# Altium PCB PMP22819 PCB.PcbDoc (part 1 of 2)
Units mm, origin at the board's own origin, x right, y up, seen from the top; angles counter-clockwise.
Board outline 101.6 x 76.2 mm, 4 copper layers (Top Layer, Mid-Layer 1, Mid-Layer 2, Bottom Layer), stack 2.286 mm thick; 108 components, 51 nets, 288 pads, 278 vias.
Unrouted connection lines stored in the file: 1.
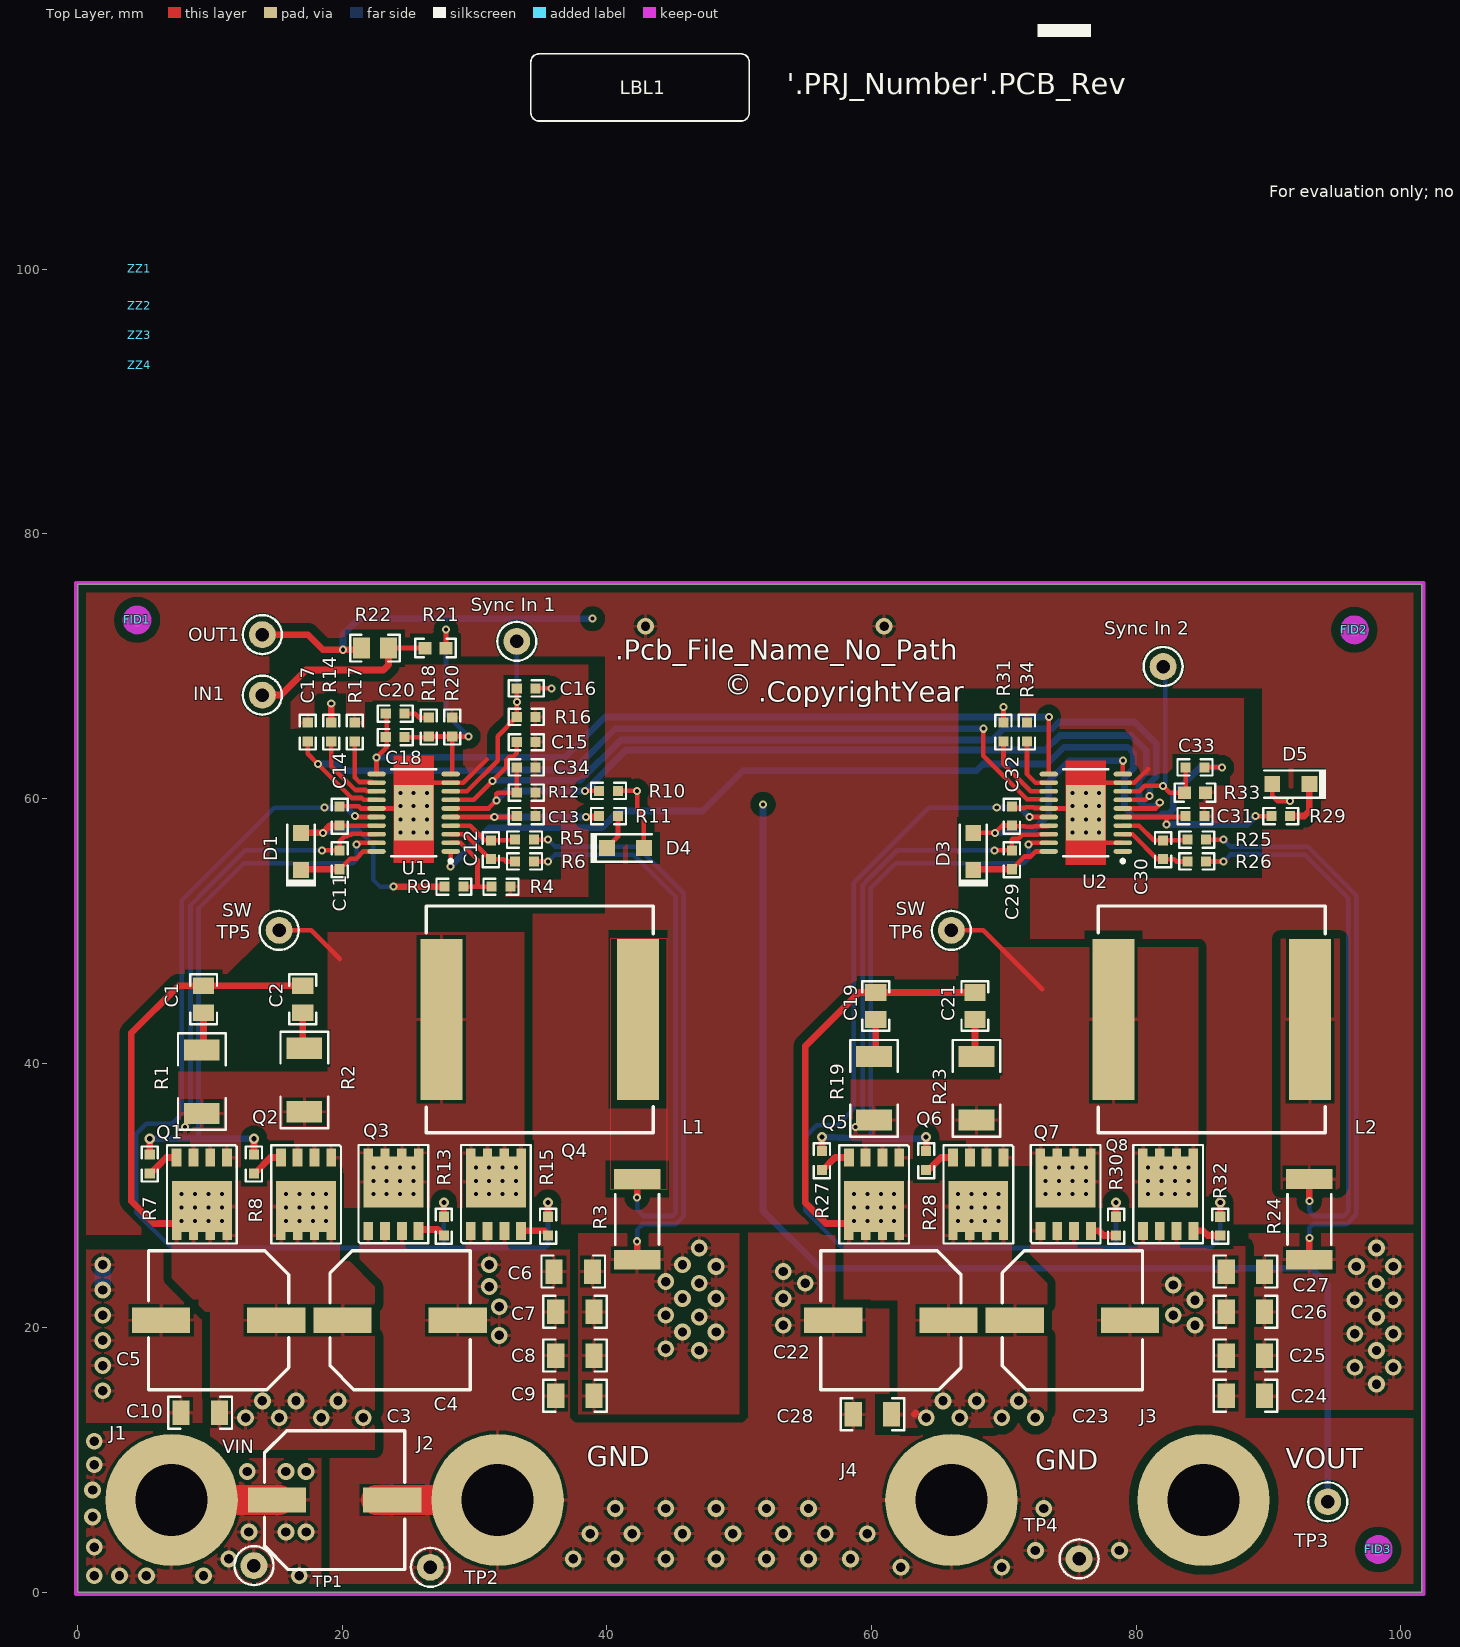
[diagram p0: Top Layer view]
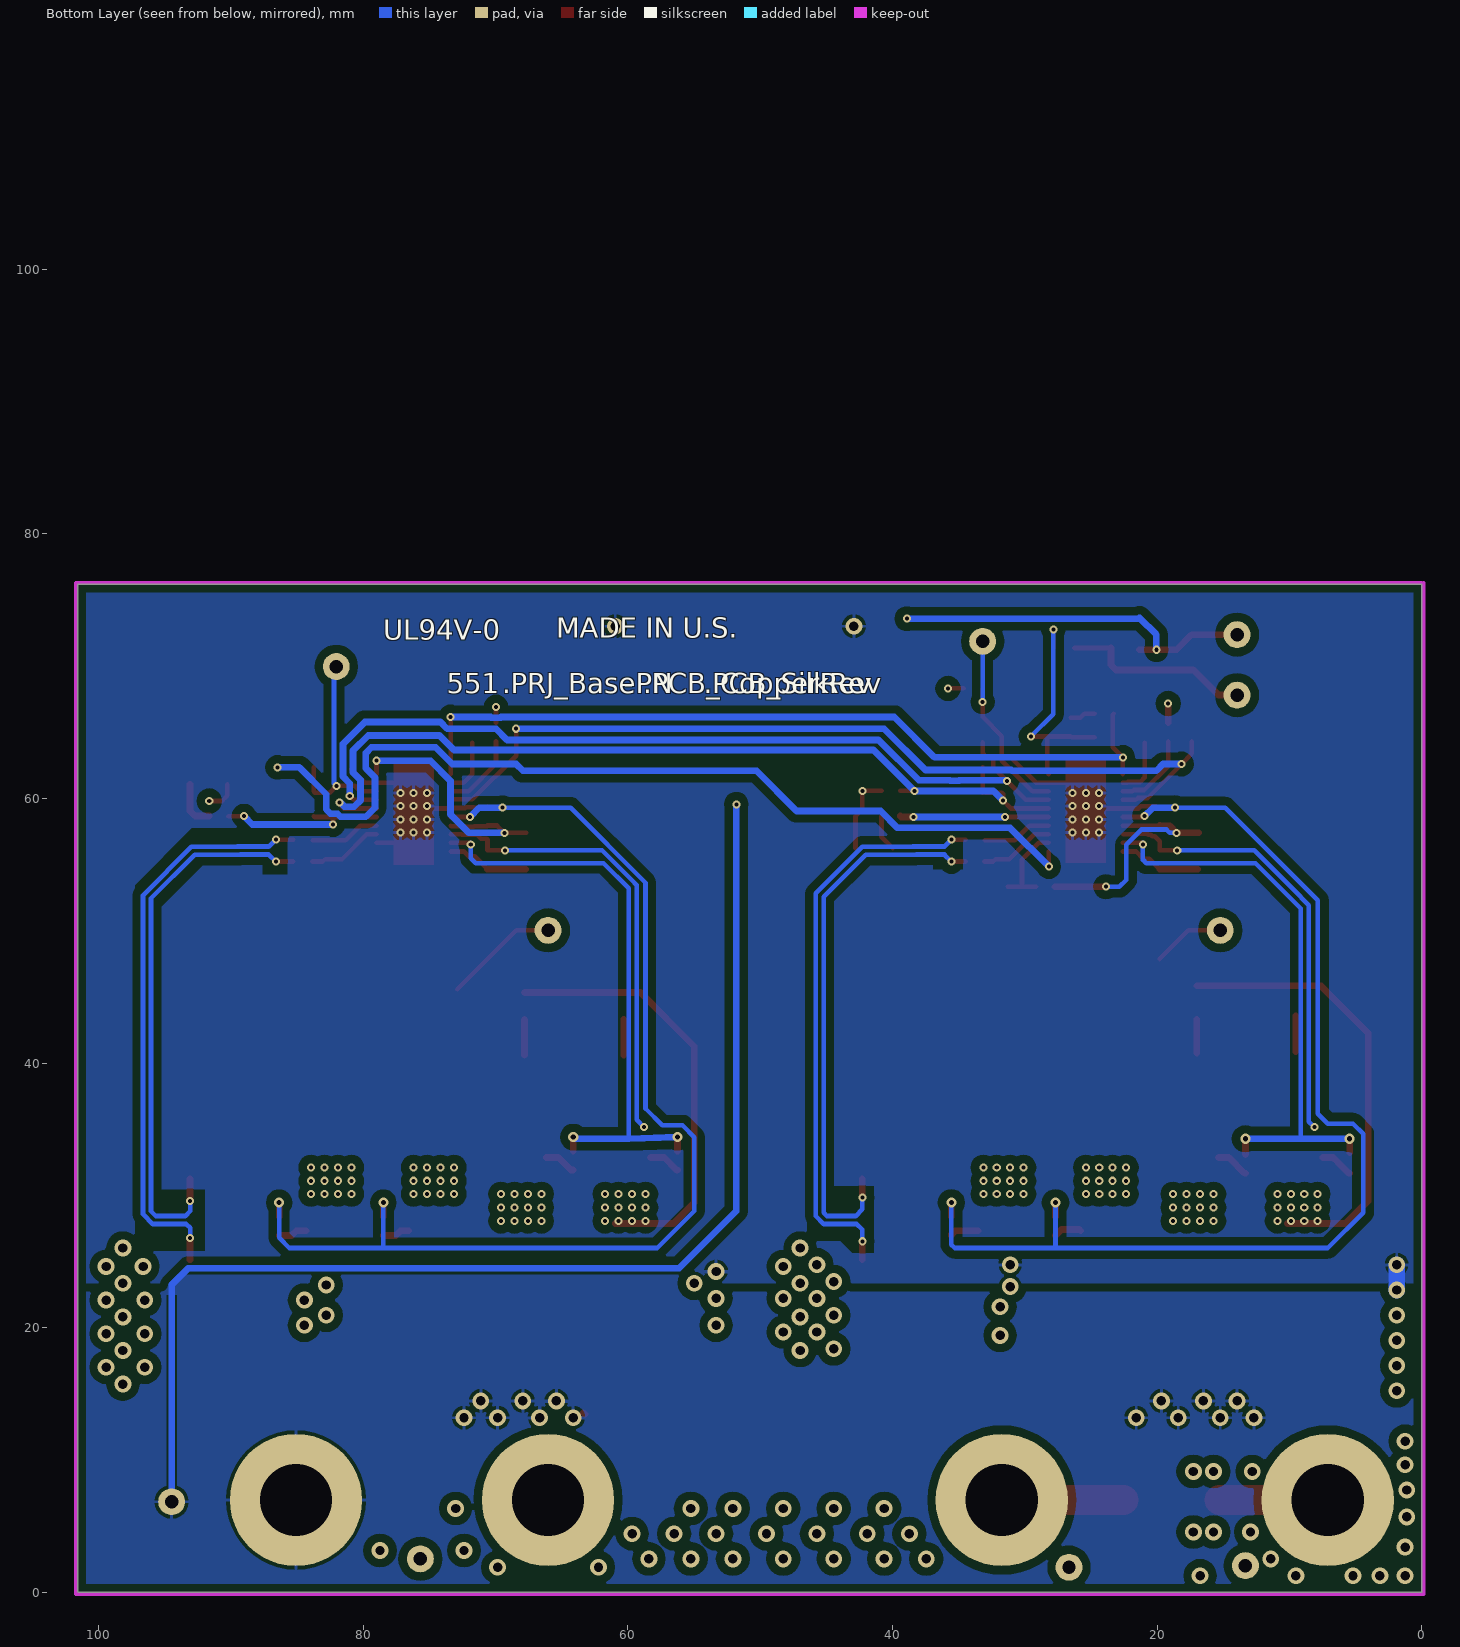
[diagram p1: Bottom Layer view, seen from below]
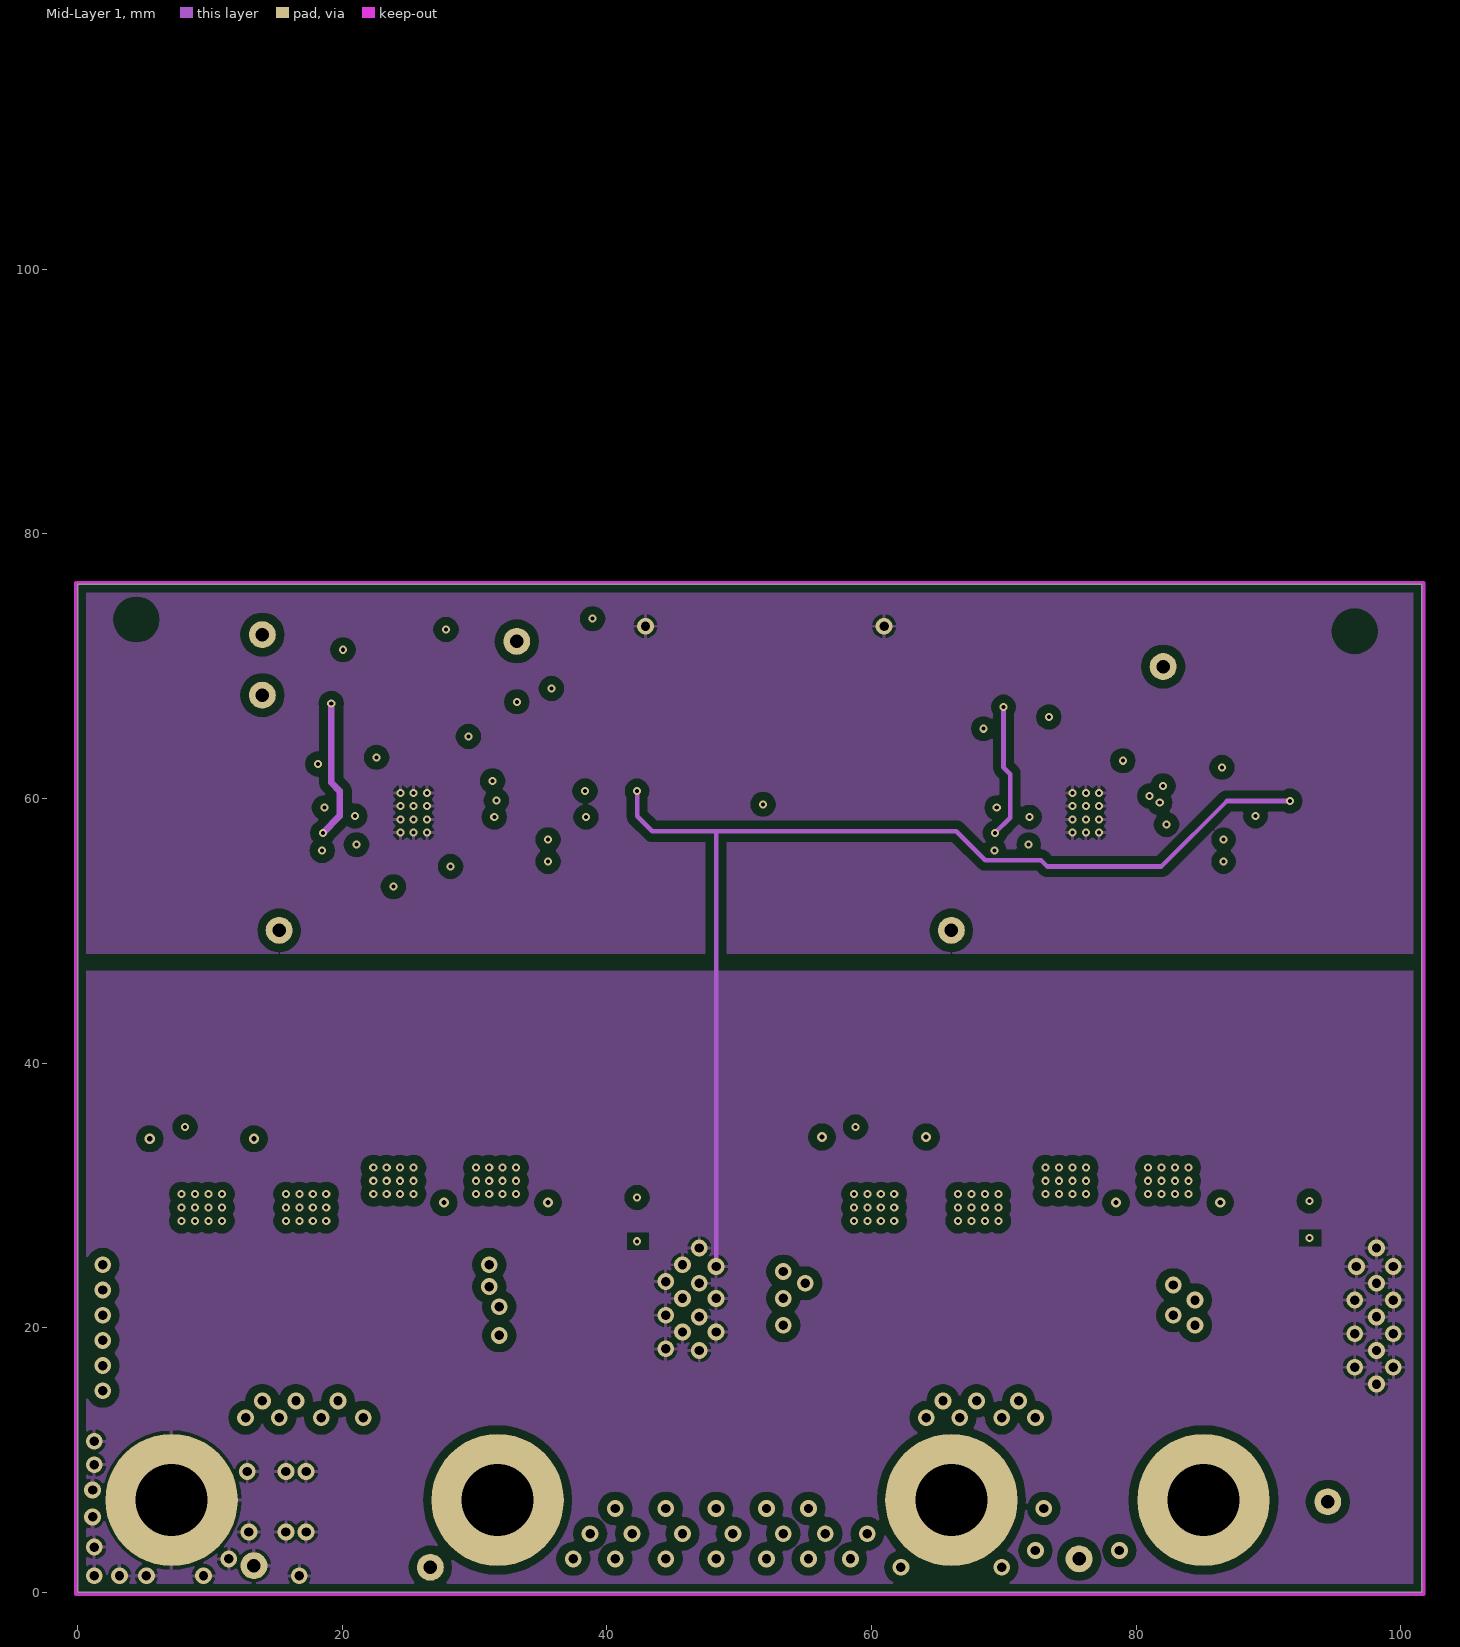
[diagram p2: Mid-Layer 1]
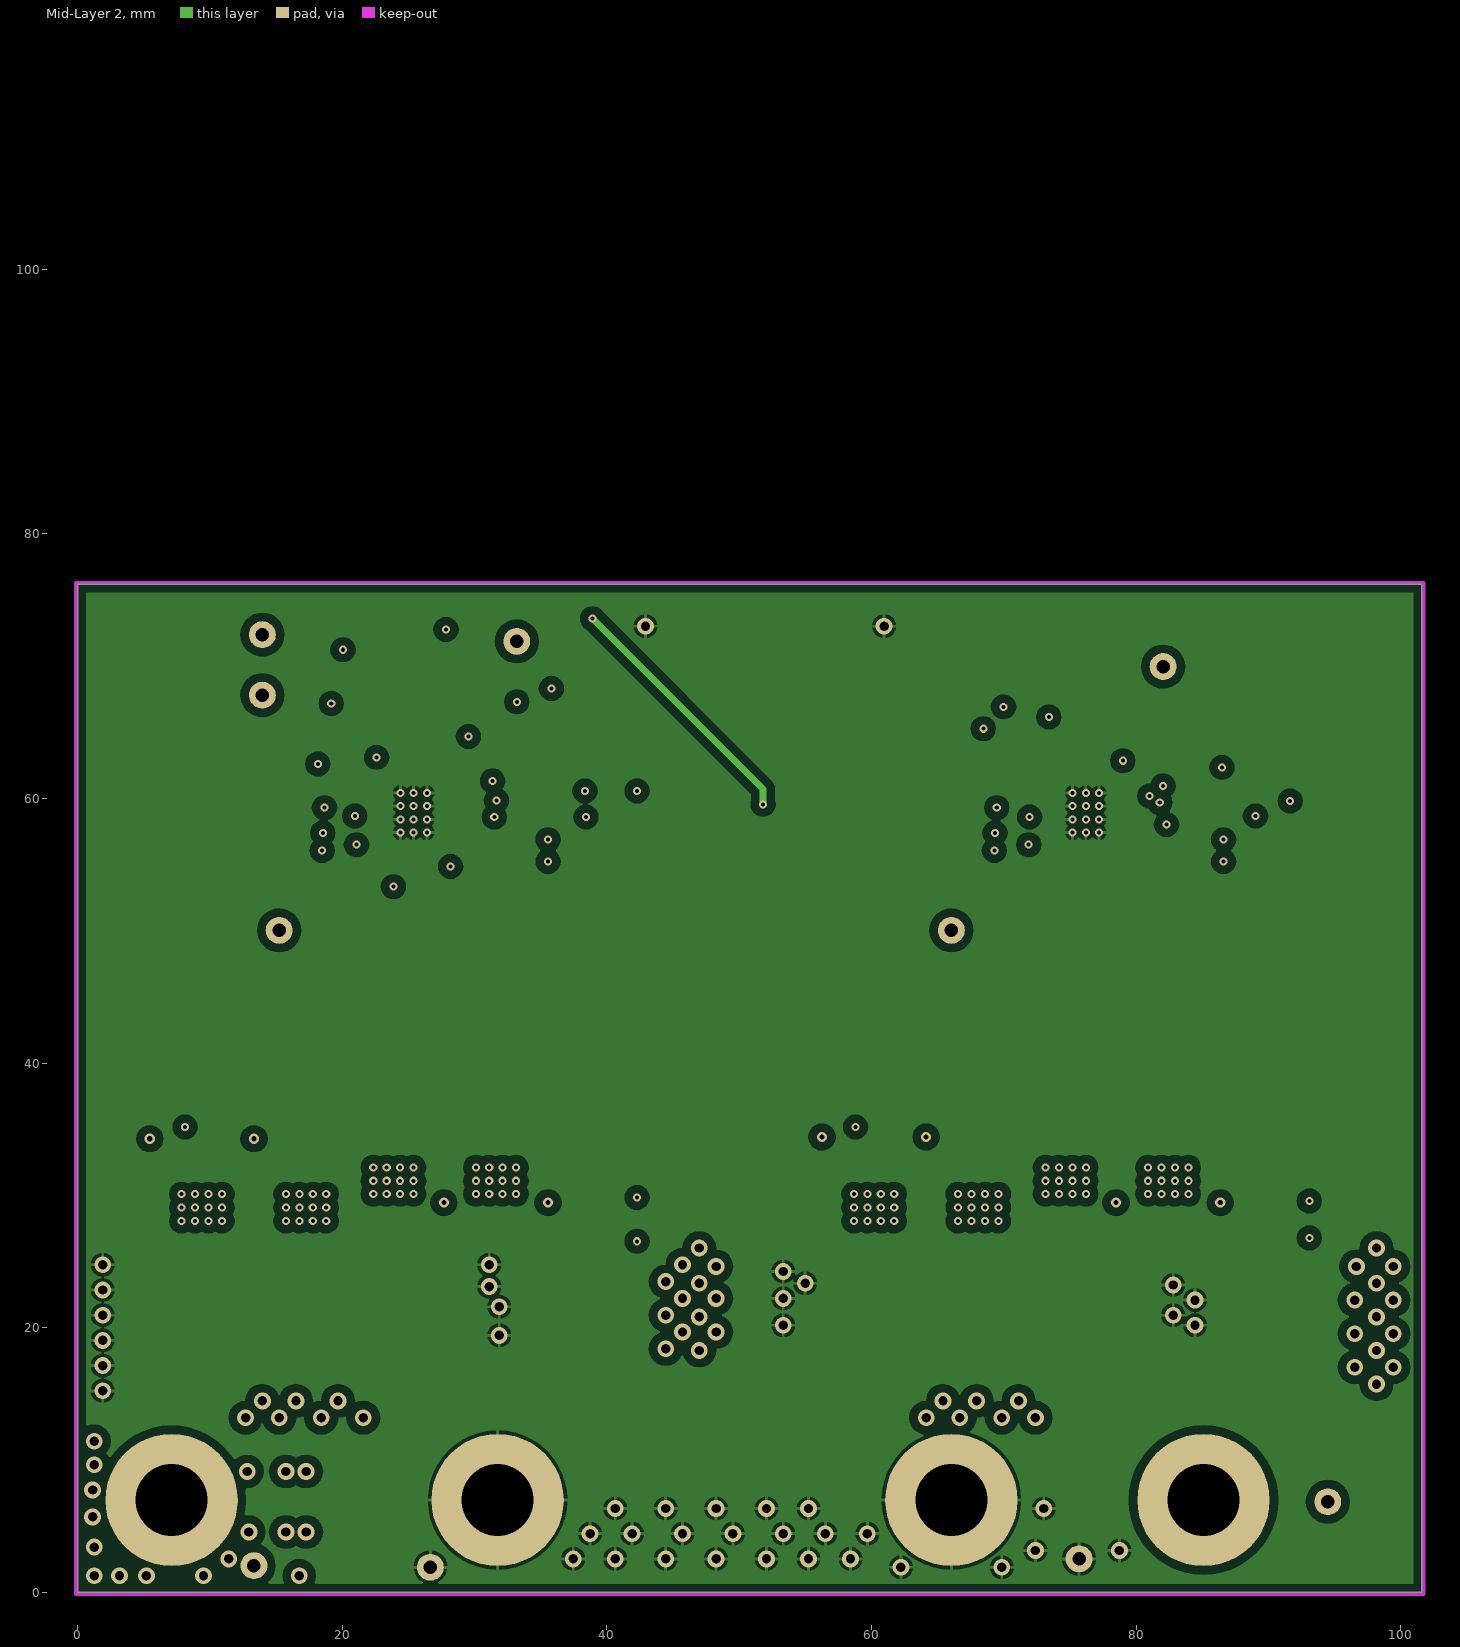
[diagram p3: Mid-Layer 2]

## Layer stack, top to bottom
Top Solder: solder mask 0.0102, Solder Resist, Dk 3.5
Top Layer: signal copper 0.0356
Dielectric1: core 1.5037, FR-4, Dk 4.8
Mid-Layer 1: signal copper 0.0356
Dielectric2: dielectric 0.32, FR-4, Dk 4.8
Mid-Layer 2: signal copper 0.0356
Dielectric3: dielectric 0.32, FR-4, Dk 4.8
Bottom Layer: signal copper 0.0356
Bottom Solder: solder mask 0.0102, Solder Resist, Dk 3.5

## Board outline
0,0 101.6,0 101.6,76.2 0,76.2

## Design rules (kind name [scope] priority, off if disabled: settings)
AcuteAngle [All] p1: minimum=4.50000000000000E+0001 checktracksonly=FALSE
AssemblyTestPointUsage [All] p1: valid=2
BoardOutlineClearance BoardOutlineClearance_MountingHoles [OnCopper and InComponentClass('Mounting Holes')] p1: gap=1 ignorepadtopadclearanceinfootprint=FALSE
BoardOutlineClearance BoardOutlineClearance_Poly [OnCopper and IsPoly] p2: gap=0.635 ignorepadtopadclearanceinfootprint=FALSE
BoardOutlineClearance [OnCopper and Not InComponentClass('Logo') and not InComponentClass('FiducialMark') and not InRegion(1000,500,4000,800) and not InPoly] p3: gap=1.905 ignorepadtopadclearanceinfootprint=FALSE
Clearance Clearance_Keepouts [((IsTrack Or IsArc) And Not InPoly) And IsFree and IsKeepOut vs ((IsTrack Or IsArc) And Not InPoly) And IsFree and IsKeepOut] p1: gap=0 ignorepadtopadclearanceinfootprint=FALSE
Clearance Clearance_Poly [InPolygon] p2: gap=0.635 ignorepadtopadclearanceinfootprint=TRUE
Clearance Clearance_FiducialMark [IsKeepOut and InComponentClass('FiducialMark') vs IsPad and InComponentClass('FiducialMark')] p3: gap=0 ignorepadtopadclearanceinfootprint=FALSE
Clearance [All] p4: gap=0.2 ignorepadtopadclearanceinfootprint=TRUE
ComponentClearance ComponentClearance_MountingHoles_FiducialMarks [InComponentClass('Mounting Holes') vs InComponentClass('FiducialMark')] p1: gap=1.27 collisioncheckmode=3 verticalgap=0.254 showdistances=FALSE
ComponentClearance ComponentClearance_Shunt [InComponentClass('Header') vs InComponentClass('Shunt')] p2: gap=0 collisioncheckmode=3 verticalgap=0 showdistances=FALSE
ComponentClearance ComponentClearance_Logo [InComponentClass('Logo')] p3: gap=1.27 collisioncheckmode=3 verticalgap=0.254 showdistances=FALSE
ComponentClearance ComponentClearance_ScrewToNut [(HasFootprint('NY PMS 440 0025 PH')) vs (HasFootprint('Keystone_1902C'))] p4: gap=0.127 collisioncheckmode=3 verticalgap=0.254 showdistances=FALSE
ComponentClearance ComponentClearance_MountingHoles [InComponentClass('Mounting Holes')] p5: gap=6.35 collisioncheckmode=3 verticalgap=2540 showdistances=FALSE
ComponentClearance ComponentClearance_SmallPassives [HasFootprint('0201*') or HasFootprint('0402*') or HasFootprint('0508') or HasFootprint('0603*') or HasFootprint('0612') or HasFootprint('0805*') or HasFootprint('0815*') or HasFootprint('0830*') or HasFootprint('1206*') or HasFootprint('1210*') or HasFootprint('1808*') or HasFootprint('1812*') or HasFootprint('1825*') or HasFootprint('2010*') or HasFootprint('2220*') or HasFootprint('2225*') or HasFootprint('2512*') or HasFootprint('2728*') or HasFootprint('3518*') vs HasFootprint('0201*') or HasFootprint('0402*') or HasFootprint('0508') or HasFootprint('0603*') or HasFootprint('0612') or HasFootprint('0805*') or HasFootprint('0815*') or HasFootprint('0830*') or HasFootprint('1206*') or HasFootprint('1210*') or HasFootprint('1808*') or HasFootprint('1812*') or HasFootprint('1825*') or HasFootprint('2010*') or HasFootprint('2220*') or HasFootprint('2225*') or HasFootprint('2512*') or HasFootprint('2728*') or HasFootprint('3518*')] p6: gap=0.38 collisioncheckmode=3 verticalgap=0.254 showdistances=FALSE
ComponentClearance ComponentClearance_THtoSMT [IsThruComponent vs IsSMTComponent] p7: gap=1.016 collisioncheckmode=3 verticalgap=0.762 showdistances=FALSE
ComponentClearance ComponentClearance_THtoTH [IsThruComponent vs IsThruComponent] p8: gap=0.762 collisioncheckmode=3 verticalgap=0.762 showdistances=FALSE
ComponentClearance [All] p9: gap=0.762 collisioncheckmode=3 verticalgap=0.254 showdistances=FALSE
DiffPairsRouting [All] p1: maxlimit=2.54 minlimit=0.254 mostfreqgap=0.254 toplayer_minwidth=0.381 toplayer_maxwidth=0.381 toplayer_prefwidth=0.381 midlayer1_minwidth=0.381 midlayer1_maxwidth=0.381 midlayer1_prefwidth=0.381 midlayer2_minwidth=0.381 midlayer2_maxwidth=0.381 midlayer2_prefwidth=0.381 bottomlayer_minwidth=0.381 bottomlayer_maxwidth=0.381 bottomlayer_prefwidth=0.381 maxuncoupledlength=25.4
FabricationTestPointUsage TestPointUsage [All] p1: valid=2 allowmultiple=FALSE
FabricationTestpoint Testpoint [All] p1: side=3 testpointundercomponent=TRUE minsize=1.016 maxsize=2.54 preferedsize=1.524 minholesize=0 maxholesize=1.016 preferedholesize=0.813 testpointgrid=0.025 allowsidetop=TRUE allowsidebottom=TRUE usegrid=TRUE gridtolerance=0
FanoutControl Fanout_LCC [IsLCC] p1: bgadir=Out bgaviamode=Centered fanoutstyle=Auto fanoutdirection=Alternating viagrid=0.025 // Fanout_LCC (Default Rule)
FanoutControl Fanout_BGA [IsBGA] p2: bgadir=Out bgaviamode=Centered fanoutstyle=Auto fanoutdirection=Alternating viagrid=0.025 // Fanout_BGA (Default Rule)
FanoutControl Fanout_Default [All] p4: bgadir=Out bgaviamode=Centered fanoutstyle=Auto fanoutdirection=Alternating viagrid=0.025 // Fanout_Default (Default Rule)
FanoutControl Fanout_Small [(CompPinCount < 5)] p5: bgadir=Out bgaviamode=Centered fanoutstyle=Auto fanoutdirection=OutThenIn viagrid=0.025 // Fanout_Small (Default Rule)
HoleSize [All] p1: absolutevalues=TRUE maxlimit=6.375 minlimit=0.2 maxpercent=80.000 minpercent=20.000
MinimumAnnularRing MinimumAnnularRing_ThermalPadVias [IsVia and InAnyComponent] p1: minimumring=0.15
MinimumAnnularRing [All] p2: minimumring=0.2
MinimumSolderMaskSliver MinimumSolderMaskSliver_Logo [InComponentClass('Logo') vs InComponentClass('Logo')] p1: minsoldermaskwidth=0.018
MinimumSolderMaskSliver [All] p2: minsoldermaskwidth=0.1
PlaneConnect [All] p1: planeconnectstyle=Relief reliefexpansion=0.254 reliefentries=4 reliefconductorwidth=0.254 reliefairgap=0.254
PolygonConnect [All] p1: connectstyle=Relief reliefconductorwidth=0.254 reliefentries=4 polygonreliefangle="90 Angle" airgapwidth=0.254
RoutingLayers [All] p1: top layer_v5=TRUE mid layer 1_v5=FALSE mid layer 2_v5=FALSE bottom layer_v5=TRUE
RoutingVias ThermalPadVias [IsVia and InAnyComponent] p1: holewidth=0.2 width=0.5 viastyle="Through Hole" minholewidth=0.2 minwidth=0.5 maxholewidth=0.33 maxwidth=0.6
RoutingVias [All] p2: holewidth=0.406 width=0.864 viastyle="Through Hole" minholewidth=0.2 minwidth=0.66 maxholewidth=1.016 maxwidth=1.651
SilkToBoardRegionClearance [Not ((IsComment or IsDesignator) And (Hide <> 'False')) and not InRegion(1000,500,4000,800)] p1:
SilkToSilkClearance SilkToSilkClearance_Pb-FreeLogo [(HasFootprint('Pb-Free_Overlay_Medium') OR HasFootprint('Pb-Free_Overlay_Small')) vs (HasFootprint('Pb-Free_Overlay_Medium') OR HasFootprint('Pb-Free_Overlay_Small'))] p1: silktosilkclearance=0
SilkToSilkClearance [All] p2: silktosilkclearance=0.1
SilkToSolderMaskClearance SilkToComponentPadClearance [(IsPad or IsFill or IsRegion) and InAnycomponent] p1: minsilkscreentomaskgap=0.127 clearancetoexposedcopper=TRUE
SilkToSolderMaskClearance "Silk to Solder Mask Opening" [All] p2: minsilkscreentomaskgap=0.1 clearancetoexposedcopper=FALSE
SolderMaskExpansion [All] p1: expansion=0.05
UnRoutedNet [All] p1: checkbadconnections=TRUE
Width [All] p1: maxlimit=2.54 minlimit=0.152 preferedwidth=0.254 checkconnectedcopper=TRUE
13 further rules are at their usual default settings.

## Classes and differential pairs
component class PMP22819: C1 C2 C3 C4 C5 C6 C7 C8 C9 C10 C11 C12 C13 C14 C15 C16 C17 C18 C19 C20 C21 C22 C23 C24 C25 C26 C27 C28 C29 C30 C31 C32 C33 C34 D1 D3 D4 D5 IN1 J1 J2 J3 J4 L1 L2 OUT1 Q1 Q2 Q3 Q4 Q5 Q6 Q7 Q8 R1 R2 R3 R4 R5 R6 R7 R8 R9 R10 R11 R12 R13 R14 R15 R16 R17 R18 R19 R20 R21 R22 R23 R24 R25 R26 R27 R28 R29 R30 R31 R32 R33 R34 "Sync In 1" "Sync In 2" TP1 TP2 TP3 TP4 TP5 TP6 U1 U2
component class "PMP22819 Hardware": FID1 FID2 FID3 LBL1 Logo3 Logo4 ZZ1 ZZ2 ZZ3 ZZ4
component class FiducialMark: FID1 FID2 FID3
component class AssemblyNote: ZZ1 ZZ2 ZZ3 ZZ4
component class Label: LBL1
differential pair SW2: +SW2_P -SW2_N
differential pair SW1: +SW1_P -SW1_N

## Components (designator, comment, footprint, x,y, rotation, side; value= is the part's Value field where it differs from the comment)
C1 "GRM2165C2A471JA01D" 0805_HV 9.525,44.831 r270 top value=470pF
C2 "GRM2165C2A471JA01D" 0805_HV 17.018,44.831 r270 top value=470pF
C3 "10SVPS330M" SVPS_F8 19.431,6.985 r0 top value=330uF
C4 "16SVP180MX" SVP_F8 24.384,20.574 r0 top value=180uF
C5 "16SVP180MX" SVP_F8 10.668,20.574 r180 top value=180uF
C6 "C3216X5R1C106M" 1206 37.465,24.257 r180 top value=10uF
C7 "C3216X5R1C106M" 1206 37.592,21.209 r180 top value=10uF
C8 "C3216X5R1C106M" 1206 37.592,17.907 r180 top value=10uF
C9 "C3216X5R1C106M" 1206 37.592,14.859 r180 top value=10uF
C10 "C3216X5R1C106M" 1206 9.271,13.589 r180 top value=10uF
C11 "GRM188R71E474KA12D" 0603_HV 19.812,55.372 r270 top value=0.47uF
C12 "GRM1885C1H101JA01D" 0603_HV 31.242,56.134 r90 top value=100pF
C13 "GRM188R71E474KA12D" 0603_HV 33.909,58.674 r0 top value=0.47uF
C14 "GRM188R71E105KA12D" 0603_HV 19.812,58.674 r90 top value=1uF
C15 "GRM188R71E104KA01D" 0603_HV 33.909,64.262 r0 top value=0.1uF
C16 "GRM1885C1H101JA01D" 0603_HV 33.909,68.326 r180 top value=100pF
C17 "GRM188R71E473KA01D" 0603_HV 17.399,65.024 r90 top value=0.047uF
C18 "GRM1885C1H101JA01D" 0603_HV 24.003,64.643 r180 top value=100pF
C19 "GRM2165C2A471JA01D" 0805_HV 60.325,44.323 r270 top value=470pF
C20 "C0603C223K3RACTU" 0603_HV 24.003,66.421 r180 top value=0.022uF
C21 "GRM2165C2A471JA01D" 0805_HV 67.818,44.323 r270 top value=470pF
C22 "16SVP180MX" SVP_F8 61.468,20.574 r180 top value=180uF
C23 "16SVP180MX" SVP_F8 75.184,20.574 r0 top value=180uF
C24 "C3216X5R1C106M" 1206 88.265,14.859 r180 top value=10uF
C25 "C3216X5R1C106M" 1206 88.265,17.907 r180 top value=10uF
C26 "C3216X5R1C106M" 1206 88.265,21.209 r180 top value=10uF
C27 "C3216X5R1C106M" 1206 88.265,24.257 r180 top value=10uF
C28 "C3216X5R1C106M" 1206 60.071,13.462 r180 top value=10uF
C29 "GRM188R71E474KA12D" 0603_HV 70.612,55.372 r270 top value=0.47uF
C30 "GRM1885C1H101JA01D" 0603_HV 82.042,56.134 r90 top value=100pF
C31 "GRM188R71E474KA12D" 0603_HV 84.455,58.674 r0 top value=0.47uF
C32 "GRM188R71E105KA12D" 0603_HV 70.612,58.674 r90 top value=1uF
C33 "GRM1885C1H101JA01D" 0603_HV 84.455,62.357 r180 top value=100pF
C34 "GRM188R71C103KA01D" 0603_HV 33.909,62.357 r0 top value=0.01uF
D1 "PMEG6010CEH,115" SOD-123F 16.891,56.007 r90 top value=0.57V
D3 "PMEG6010CEH,115" SOD-123F 67.691,56.007 r90 top value=0.57V
D4 "PMEG6010CEH,115" SOD-123F 41.402,56.261 r0 top value=0.57V
D5 "PMEG6010CEH,115" SOD-123F 91.694,61.087 r180 top value=0.57V
FID1 "Fiducial" Fiducial10-20 4.5,73.5 r0 top
FID2 "Fiducial" Fiducial10-20 96.5,72.75 r0 top
FID3 "Fiducial" Fiducial10-20 98.298,3.25 r0 top
IN1 "5002" Keystone5002 13.97,67.818 r0 top value=White
J1 "575-4" Keystone_575-4 7.112,6.985 r0 top
J2 "575-4" Keystone_575-4 31.75,6.985 r0 top
J3 "575-4" Keystone_575-4 85.09,6.985 r0 top
J4 "575-4" Keystone_575-4 66.04,6.985 r0 top
L1 "IHLP6767GZER3R3MA1" IHLP6767GZ 34.925,43.307 r180 top value=3.3uH
L2 "IHLP6767GZER3R3MA1" IHLP6767GZ 85.725,43.307 r180 top value=3.3uH
LBL1 "THT-14-423-10" Label_650x200 42.513,113.742 r0 top
Logo3 "FCC disclaimer" FCC_disclaimer 106,105.5 r0 top
Logo4 "WEEE logo" WEEE_Minimum 74.568,121.946 r0 top
OUT1 "5002" Keystone5002 13.97,72.39 r0 top value=White
Q1 "CSD16415Q5" "Q5A WITH VIAS" 9.398,30.099 r270 top value=25V
Q2 "CSD16415Q5" "Q5A WITH VIAS" 17.272,30.099 r270 top value=25V
Q3 "CSD16415Q5" "Q5A WITH VIAS" 23.876,30.099 r90 top value=25V
Q4 "CSD16415Q5" "Q5A WITH VIAS" 31.623,30.099 r90 top value=25V
Q5 "CSD16415Q5" "Q5A WITH VIAS" 60.198,30.099 r270 top value=25V
Q6 "CSD16415Q5" "Q5A WITH VIAS" 68.072,30.099 r270 top value=25V
Q7 "CSD16415Q5" "Q5A WITH VIAS" 74.676,30.099 r90 top value=25V
Q8 "CSD16415Q5" "Q5A WITH VIAS" 82.423,30.099 r90 top value=25V
R1 "ERJ-12ZYJ7R5U" 2010M 9.398,38.608 r270 top value=7.5
R2 "ERJ-12ZYJ7R5U" 2010M 17.145,38.735 r270 top value=7.5
R3 "ERJ-M1WTF1M5U" 2512M 42.291,28.194 r90 top value=0.0015
R4 "ERJ-3GEY0R00V" 0603_HV 32.004,53.34 r180 top value=0
R5 "CRCW0603100RFKEA" 0603_HV 33.782,56.896 r0 top value=100
R6 "CRCW0603100RFKEA" 0603_HV 33.782,55.245 r0 top value=100
R7 "ERJ-3GEY0R00V" 0603_HV 5.461,32.385 r90 top value=0
R8 "ERJ-3GEY0R00V" 0603_HV 13.335,32.385 r90 top value=0
R9 "CRCW0603158KFKEA" 0603_HV 28.448,53.34 r180 top value=158k
R10 "CRCW060349K9FKEA" 0603_HV 40.132,60.579 r0 top value=49.9k
R11 "CRCW06033R30JNEA" 0603_HV 40.132,58.674 r0 top value=3.3
R12 "RC0603FR-0715KL" 0603_HV 33.909,60.452 r180 top value=15.0k
R13 "ERJ-3GEY0R00V" 0603_HV 27.686,27.686 r90 top value=0
R14 "ERJ-3GEY0R00V" 0603_HV 19.177,65.024 r90 top value=0
R15 "ERJ-3GEY0R00V" 0603_HV 35.56,27.686 r90 top value=0
R16 "CRCW060320K0FKEA" 0603_HV 33.909,66.167 r180 top value=20.0k
R17 "RC0603FR-0739KL" 0603_HV 20.955,65.024 r270 top value=39.0k
R18 "CRCW060315K0FKEA" 0603_HV 26.543,65.405 r90 top value=15.0k
R19 "ERJ-12ZYJ7R5U" 2010M 60.198,38.1 r270 top value=7.5
R20 "CRCW06032K67FKEA" 0603_HV 28.321,65.405 r90 top value=2.67k
R21 "CRCW060323K2FKEA" 0603 27.051,71.374 r180 top value=23.2k
R22 "CRCW0805604RFKEA" 0805_HV 22.479,71.374 r0 top value=604
R23 "ERJ-12ZYJ7R5U" 2010M 67.945,38.1 r270 top value=7.5
R24 "ERJ-M1WTF1M5U" 2512M 93.091,28.194 r90 top value=0.0015
R25 "CRCW0603100RFKEA" 0603_HV 84.582,56.896 r0 top value=100
R26 "CRCW0603100RFKEA" 0603_HV 84.582,55.245 r0 top value=100
R27 "ERJ-3GEY0R00V" 0603_HV 56.261,32.639 r90 top value=0
R28 "ERJ-3GEY0R00V" 0603_HV 64.135,32.639 r90 top value=0
R29 "CRCW06033R30JNEA" 0603_HV 90.932,58.674 r0 top value=3.3
R30 "ERJ-3GEY0R00V" 0603_HV 78.486,27.686 r90 top value=0
R31 "ERJ-3GEY0R00V" 0603_HV 69.977,65.024 r90 top value=0
R32 "ERJ-3GEY0R00V" 0603_HV 86.36,27.686 r90 top value=0
R33 "CRCW060320K0FKEA" 0603 84.455,60.452 r180 top value=20.0k
R34 "RC0603FR-0739KL" 0603_HV 71.755,65.024 r270 top value=39.0k
"Sync In 1" "5002" Keystone5002 33.198,71.882 r0 top value=White
"Sync In 2" "5002" Keystone5002 82.042,69.977 r90 top value=White
TP1 "VIN" Keystone5000 13.335,2.032 r0 top value=Red
TP2 "GND" Keystone5001 26.67,1.905 r90 top value=Black
TP3 "VOUT" Keystone5000 94.488,6.858 r90 top value=Red
TP4 "GND" Keystone5001 75.692,2.54 r90 top value=Black
TP5 "5002" Keystone5002 15.24,50.038 r0 top value=White
TP6 "5002" Keystone5002 66.04,50.038 r0 top value=White
U1 "LM5122MH" "MXA20A_L - 10milVia" 25.4,58.928 r180 top
U2 "LM5122MH" "MXA20A_L - 10milVia" 76.2,58.928 r180 top
ZZ1 "This Assembly Note is for PCB labels only" AssemblyNoteLabel 4.699,100.025 r0 top
ZZ2 "These assemblies are ESD sensitive, ESD precautions shall be observed." AssemblyNote 4.699,97.259 r0 top
ZZ3 "These assemblies must be clean and free from flux and all contaminants. Use of no clean flux is not acceptable." AssemblyNote 4.699,95.01 r0 top
ZZ4 "These assemblies must comply with workmanship standards IPC-A-610 Class 2, unless otherwise specified." AssemblyNote 4.699,92.761 r0 top

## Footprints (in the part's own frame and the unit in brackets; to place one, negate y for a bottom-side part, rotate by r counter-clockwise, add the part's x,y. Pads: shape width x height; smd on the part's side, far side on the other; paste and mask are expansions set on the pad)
0603 [mm] "0603 from SM-752 data"
  rect 1x0.95 smd: 1(-0.8,0) 2(0.8,0)
  silkscreen extent -1.52,-0.69 1.52,0.69, body extent -0.87,-0.47 0.87,0.47, height 0.85
0603_HV [mil] "Ernesto recommended land pattern.  26 mil between pads."
  rect 30x30 smd: 1(-28,0) 2(28,0)
  silkscreen extent -52,-24 52,24, body extent -34,-19 34,19, height 33
0805_HV [mil] "0805 with 30mil clearance between pads"
  rect 50x63 smd: 1(-40,0) 2(40,0)
  silkscreen extent -74,-40 74,40, body extent -43,-29 43,29, height 43
1206 [mm] "1206 from SM-752 data"
  rect 1.3x1.85 smd: 1(-1.45,0) 2(1.45,0)
  silkscreen extent -2.4,-1.21 2.4,1.21, body extent -1.7,-0.9 1.7,0.9, height 1.35
2010M [mm]
  rect 1.6x2.7 smd: 1(-2.4,0) 2(2.4,0)
  silkscreen extent -3.65,-1.8 3.65,1.8, body extent -2.73,-1.45 2.73,1.45, height 1.66
2512M [mm] "Chip Resistor, Body 6.3x3.2mm, IPC Low Density"
  rect 1.5x3.5 smd: 1(-3.05,0) 2(3.05,0)
  silkscreen extent -1.9,-1.65 1.9,1.65, body extent -3.22,-1.67 3.22,1.67, height 0.71
AssemblyNote [mm] "Assembly Note"
AssemblyNoteLabel [mm] "Assembly Note for PCB Labels"
FCC_disclaimer [mm]
Fiducial10-20 [mm]
  round 1 smd mask+0.5: 1(0,0)
  Top Layer keep-out circle w1.178: c0,0 r0.5
IHLP6767GZ [mm] "IHLP6767GZ VISHAY DALE INDUCTOR"
  rect 3.175x12.19 smd: 1(-7.428,0) 2(7.428,0)
  silkscreen extent -8.57,-8.57 8.57,8.57, body extent -8.62,-8.6 8.67,8.67, height 7
Keystone5000 [mil] "For Keystone 500x miniature loop terminals"
  round 80 hole 40: 1(0,0)
  silkscreen extent -58,-58 58,58, body extent -49,-49 49,49, height 182
Keystone5001 [mil] "For Keystone 500x miniature loop terminals"
  round 80 hole 40: 1(0,0)
  silkscreen extent -58,-58 58,58, body extent -49,-49 49,49, height 182
Keystone5002 [mil] "For Keystone 500x miniature loop terminals"
  round 80 hole 40: 1(0,0)
  silkscreen extent -58,-58 58,58, body extent -49,-49 49,49, height 182
Keystone_575-4 [mm] "Banana Jack"
  round 10 hole 5.45: 1(0,0)
  body extent -3.95,-3.95 3.92,3.93, height 2.36
Label_650x200 [mil] "Thermal Transfer Label"
  round 1 on Mech13: 0(0,0)
  silkscreen extent -325,-100 325,100, body extent -325,-100 325,100, height 1
"MXA20A_L - 10milVia" [mm] "TSOP, 20-Leads, Body 6.5x4.4mm, Pitch 0.65mm, Exposed Pad, IPC High Density"
  oval 1.4x0.35 smd: 1(-2.8,2.925) 2(-2.8,2.275) 3(-2.8,1.625) 4(-2.8,0.975) 5(-2.8,0.325) 6(-2.8,-0.325) 7(-2.8,-0.975) 8(-2.8,-1.625) 9(-2.8,-2.275) 10(-2.8,-2.925) 11(2.8,-2.925) 12(2.8,-2.275) 13(2.8,-1.625) 14(2.8,-0.975) 15(2.8,-0.325) 16(2.8,0.325) 17(2.8,0.975) 18(2.8,1.625) 19(2.8,2.275) 20(2.8,2.925)
  rect 3x4.2 smd: 21(0,0)
  silkscreen extent -2.93,-3.3 1.7,3.77, body extent -2.25,-3.3 2.25,3.3, height 1.1
"Q5A WITH VIAS" [mm] "TI 15A WITH VIAS"
  round 0.3 on Top Overlay: 0(-2.766,3.087)
  rect 1.372x0.75 smd paste-0.1 mask+0.051: 1(-2.77,1.905) 2(-2.77,0.635) 3(-2.77,-0.635) 4(-2.77,-1.905)
  rect 0.675x0.71 smd paste-0.1 mask+0.051: 5(3.134,-1.905) 6(3.134,-0.635) 7(3.134,0.635) 8(3.134,1.905)
  rect 3.85x4.52 smd paste-2.2 mask+0.051: 9(0.939,0)
  silkscreen extent -3.71,-2.63 3.72,2.64, body extent -3.05,-2.5 3.05,2.5, height 1.11
SOD-123F [mm] "NXP recommended land pattern"
  rect 1.2x1.2 smd paste-0.05: 1(-1.4,0) 2(1.4,0)
  silkscreen extent -2.64,-1.12 2.01,1.12, body extent -1.8,-0.85 1.8,0.85, height 1.2
SVP_F8 [mm] "SANYO SVP_F8"
  rect 4.4x1.9 smd: 1(-4.35,0) 2(4.35,0)
  silkscreen extent -5.3,-5.25 5.3,5.25, body extent -5.25,-5.23 5.33,5.2, height 8
SVPS_F8 [mm] "SANYO SVPS_F8"
  rect 4.4x1.9 smd: 1(-4.35,0) 2(4.35,0)
  silkscreen extent -5.3,-5.25 5.3,5.25, body extent -5.25,-5.23 5.33,5.2, height 8
WEEE_Minimum [mm] "WEEElie bin"
  silkscreen extent -2.42,-4.38 2.52,2.65

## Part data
C1 C2 C19 C21: "CAP, CERM, 470pF, 100V, +/-5%, C0G/NP0, 0805", Alternate Manufacturer=-, Cap_Case=0805, Manufacturer=MuRata, Supplier Part Number 1=490-1611-1-ND, TempCo=C0G/NP0, Tolerance_%=5, Value1=?, Value2=100V, ValueDisplayed=470pF
C3: "CAP, AL, 330uF, 10V, +/-20%, SMD", Alternate Manufacturer=-, Cap_Case=HA0, Manufacturer=Panasonic, Tolerance_%=20, Value1=?, Value2=25V, ValueDisplayed=330µF
C4 C5 C22 C23: "CAP, AL, 180uF, 16V, +/-20%, SMD", Alternate Manufacturer=-, Cap_Case=HA0, Manufacturer=Sanyo, Tolerance_%=20, Value1=?, Value2=16V, ValueDisplayed=180µF
C6 C7 C8 C9 C10 C24 C25 C26 C27 C28: "CAP, CERM, 10uF, 16V, +/-20%, X5R, 1206", Alternate Manufacturer=-, Cap_Case=1206, Manufacturer=TDK, Supplier Part Number 1=445-1426-1-ND, TempCo=X5R, Tolerance_%=20, Value1="0.0046 ohm", Value2=16V, ValueDisplayed=10µF
C11 C13 C29 C31: "CAP, CERM, 0.47uF, 25V, +/-10%, X7R, 0603", Alternate Manufacturer=-, Cap_Case=0603, Manufacturer=MuRata, Supplier Part Number 1=490-3291-1-ND, TempCo=X7R, Tolerance_%=10, Value1=?, Value2=25V, ValueDisplayed=0.47µF
C12 C16 C18 C30 C33: "CAP, CERM, 100pF, 50V, +/-5%, C0G/NP0, 0603", Alternate Manufacturer=-, Cap_Case=0603, Manufacturer=MuRata, Supplier Part Number 1=490-1427-1-ND, TempCo=C0G/NP0, Tolerance_%=5, Value1=?, Value2=50V, ValueDisplayed=100pF
C14 C32: "CAP, CERM, 1uF, 25V, +/-10%, X7R, 0603", Alternate Manufacturer=-, Cap_Case=0603, Manufacturer=MuRata, Supplier Part Number 1=490-5307-1-ND, TempCo=X7R, Tolerance_%=10, Value1=?, Value2=25V, ValueDisplayed=1µF
C15: "CAP, CERM, 0.1uF, 25V, +/-10%, X7R, 0603", Alternate Manufacturer=-, Cap_Case=0603, Manufacturer=MuRata, Supplier Part Number 1=490-1524-1-ND, TempCo=X7R, Tolerance_%=10, Value1=?, Value2=25V, ValueDisplayed=0.1µF
C17: "CAP, CERM, 0.047uF, 25V, +/-10%, X7R, 0603", Alternate Manufacturer=-, Cap_Case=0603, Manufacturer=MuRata, Supplier Part Number 1=490-1522-1-ND, TempCo=X7R, Tolerance_%=10, Value1=?, Value2=25V, ValueDisplayed=0.047µF
C20: "CAP, CERM, 0.022uF, 25V, +/-10%, X7R, 0603", Alternate Manufacturer=-, Cap_Case=0603, Manufacturer=Kemet, Supplier Part Number 1=399-1094-1-ND, TempCo=X7R, Tolerance_%=10, Value1=?, Value2=25V, ValueDisplayed=0.022µF
C34: "CAP, CERM, 0.01uF, 16V, +/-10%, X7R, 0603", Alternate Manufacturer=-, Cap_Case=0603, Manufacturer=MuRata, Supplier Part Number 1=490-1525-1-ND, TempCo=X7R, Tolerance_%=10, Value1=?, Value2=16V, ValueDisplayed=0.01µF
D1 D3 D4 D5: "Diode, Schottky, 60V, 1A, SOD-123F", Alternate Manufacturer=-, Manufacturer="NXP Semiconductor", Supplier Part Number 1=568-4104-1-ND, Value1=1A, Value2=60V
FID1 FID2 FID3: library part CMP-0077181-1, "Fiducial mark.  There is nothing to buy or mount.", Manufacturer=N/A
IN1 OUT1 "Sync In 1" "Sync In 2" TP5 TP6: "Test Point, TH, Miniature, White", Alternate Manufacturer=Any, Alternate PartNumber=Equivalent, DigiKeyPartNumber=5002K-ND, Manufacturer=Keystone
J1 J2 J3 J4: "Standard Banana Jack, Uninsulated, 5.5mm", Alternate Manufacturer=Any, Alternate PartNumber=Equivalent, Manufacturer=Keystone, Supplier Part Number 1=575-4K-ND
L1 L2: "INDUCTOR POWER 3.3UH 54A SMD", Alternate Manufacturer=Any, Alternate PartNumber=Equivalent, Manufacturer=Vishay-Dale, Value1="0.0018 ohm", Value2=54A, ValueDisplayed=3.3µH
LBL1: library part CMP-0003625-1, "Thermal Transfer Printable Labels, 0.650\" W x 0.200\" H - 10,000 per roll", Manufacturer=Brady, Supplier Part Number 1=97C5133
Logo3: library part CMP-0074847-1, "FCC_disclaimer"
Logo4: library part CMP-0074769-1
Q1 Q2 Q3 Q4 Q5 Q6 Q7 Q8: "MOSFET N-CH 25V 8SON", Alternate Manufacturer=-, DigiKeyPartNumber=296-30139-1-ND, Manufacturer="Texas Instruments", Value1="0.0015 ohm", Value2="21 nC"
R1 R2 R19 R23: "RESISTOR 7.5 OHM 3/4W 5% 2010", Alternate Manufacturer=-, Manufacturer=Panasonic, Power_W=1, Supplier Part Number 1=P7.5WCT-ND, TempCo="-100 /+600 ppm/C", Tolerance_%=5, Value1=5%, Value2=1W, Value_Code=7R50
R3 R24: "RES, 0.0015 ohm, 1%, 1W, 2512", Alternate Manufacturer=-, Manufacturer=Panasonic, Power_W=1, Supplier Part Number 1=P1.5NDCT-ND, TempCo=ppm/C, Value1=1%, Value2=1W, Value_Code=R0015
R4 R7 R8 R13 R14 R15 R27 R28 R30 R31 R32: "RES, 0 ohm, 5%, 0.1W, 0603", Alternate Manufacturer=-, Manufacturer=Panasonic, Power_W=0.1, Supplier Part Number 1=P0.0GCT-ND, TempCo="600 ppm/C", Tolerance_%=5, Value1=5%, Value2=0.1W, Value_Code=0000
R5 R6 R25 R26: "RES, 100 ohm, 1%, 0.1W, 0603", Alternate Manufacturer=-, Manufacturer=Vishay-Dale, Power_W=0.1, Supplier Part Number 1=541-100HCT-ND, TempCo="100 ppm/C", Tolerance_%=1, Value1=1%, Value2=0.1W, Value_Code=100R
R9: "RES, 158k ohm, 1%, 0.1W, 0603", Alternate Manufacturer=-, Manufacturer=Vishay-Dale, Power_W=0.1, Supplier Part Number 1=541-158KHCT-ND, TempCo="100 ppm/C", Tolerance_%=1, Value1=1%, Value2=0.1W, Value_Code=158k
R10: "RES, 49.9k ohm, 1%, 0.1W, 0603", Alternate Manufacturer=-, Manufacturer=Vishay-Dale, Power_W=0.1, Supplier Part Number 1=541-49.9KHCT-ND, TempCo="100 ppm/C", Tolerance_%=1, Value1=1%, Value2=0.1W, Value_Code=49k9
R11 R29: "RES, 3.3 ohm, 5%, 0.1W, 0603", Alternate Manufacturer=-, Manufacturer=Vishay-Dale, Power_W=0.1, Supplier Part Number 1=541-3.3GCT-ND, TempCo="200 ppm/C", Tolerance_%=5, Value1=5%, Value2=0.1W, Value_Code=3R30
R12: "RES, 15.0k ohm, 1%, 0.1W, 0603", Alternate Manufacturer=-, Manufacturer="Yageo America", Power_W=0.1, Supplier Part Number 1=311-15.0KHRCT-ND, TempCo="200 ppm/C", Tolerance_%=1, Value1=1%, Value2=0.1W, Value_Code=15k0
R16 R33: "RES, 20.0k ohm, 1%, 0.1W, 0603", Alternate Manufacturer=-, Manufacturer=Vishay-Dale, Power_W=0.1, Supplier Part Number 1=541-20.0KHCT-ND, TempCo="100 ppm/C", Tolerance_%=1, Value1=1%, Value2=0.1W, Value_Code=20k0
R17 R34: "RES, 39.0k ohm, 1%, 0.1W, 0603", Alternate Manufacturer=-, Manufacturer="Yageo America", Power_W=0.1, Supplier Part Number 1=311-39.0KHRCT-ND, TempCo="200 ppm/C", Tolerance_%=1, Value1=1%, Value2=0.1W, Value_Code=39k0
R18: "RES, 15.0k ohm, 1%, 0.1W, 0603", Alternate Manufacturer=-, Manufacturer=Vishay-Dale, Power_W=0.1, Supplier Part Number 1=541-15.0KHCT-ND, TempCo="100 ppm/C", Tolerance_%=1, Value1=1%, Value2=0.1W, Value_Code=15k0
R20: "RES, 2.67k ohm, 1%, 0.1W, 0603", Alternate Manufacturer=-, Manufacturer=Vishay-Dale, Power_W=0.1, Supplier Part Number 1=541-2.67KHCT-ND, TempCo="100 ppm/C", Tolerance_%=1, Value1=1%, Value2=0.1W, Value_Code=2k67
R21: "RES, 23.2k ohm, 1%, 0.1W, 0603", Alternate Manufacturer=-, Manufacturer=Vishay-Dale, Power_W=0.1, Supplier Part Number 1=541-23.2KHCT-ND, TempCo="100 ppm/C", Tolerance_%=1, Value1=1%, Value2=0.1W, Value_Code=23k2
R22: "RES, 604 ohm, 1%, 0.125W, 0805", Alternate Manufacturer=-, Manufacturer=Vishay-Dale, Power_W=0.125, Supplier Part Number 1=541-604CCT-ND, TempCo="100 ppm/C", Tolerance_%=1, Value1=1%, Value2=0.125W, Value_Code=604R
TP1 TP3: library part 5000, "Test Point, TH, Miniature, Red", Alternate Manufacturer=-, DigiKeyPartNumber=5000K-ND, Manufacturer=Keystone
TP2 TP4: library part 5001, "Test Point, TH, Miniature, Black", Alternate Manufacturer=-, DigiKeyPartNumber=5001K-ND, Manufacturer=Keystone
U1 U2: library part LM5122, Alternate Manufacturer=-, Manufacturer=TI
ZZ1: library part CMP-0003616-3
ZZ2: library part CMP-0077236-1
ZZ3: library part CMP-0077237-1
ZZ4: library part CMP-0077238-1

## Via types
v1: diameter 0.61, hole 0.305, Top Layer to Bottom Layer, 169 vias
v2: diameter 1.27, hole 0.711, Top Layer to Bottom Layer, 101 vias
v3: diameter 0.762, hole 0.381, Top Layer to Bottom Layer, 8 vias

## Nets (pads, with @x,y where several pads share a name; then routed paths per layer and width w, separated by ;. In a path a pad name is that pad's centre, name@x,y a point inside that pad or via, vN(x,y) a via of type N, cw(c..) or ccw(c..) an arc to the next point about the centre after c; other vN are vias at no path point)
BST1: C11.2 D1.1 U1.20 | length 6.2
  Top Layer w0.35: C11.2@19.812,54.661 20.612,55.461 21.066,55.461 21.608,56.003 U1.20@22.6,56.003
  Top Layer w0.508: D1.1@16.945,54.661 C11.2@19.812,54.661
BST2: C29.2 D3.1 U2.20 | length 6.2
  Top Layer w0.35: C29.2@70.612,54.661 71.577,55.626 72.031,55.626 72.408,56.003 U2.20@73.4,56.003
  Top Layer w0.508: D3.1@67.745,54.661 C29.2@70.612,54.661
COMP: C18.2 C20.2 U1.11 U2.11 | length 61.3
  Top Layer w0.35: U1.11@22.6,61.853 v1(22.6,63.113) 23.368,63.881 23.368,66.345 C20.2@23.292,66.421 ; U2.11@73.4,61.853 73.4,66.161 v1(73.406,66.167)
  Bottom Layer w0.508: v1(22.6,63.113) 36.824,63.113 39.878,66.167 69.59,66.167 69.64,66.116 70.314,66.116 70.364,66.167 v1(73.406,66.167)
CSN1: C12.1 R6.1 U1.3 | length 5.7
  Top Layer w0.35: U1.3@28.2,57.303 29.311,57.303 31.191,55.423 C12.1@31.242,55.423 32.207,55.423 32.385,55.245 R6.1@33.071,55.245
CSN1_N: L1.1 R3.2 R6.2 | length 41.7
  Top Layer w0.35: R6.2@34.493,55.245 v1(35.56,55.245)
  Top Layer w0.508: v1(42.291,29.845) R3.2@42.291,31.244
  Bottom Layer w0.35: v1(35.56,55.245) 36.083,55.768 38.227,55.768 38.242,55.753 42.037,55.753 45.212,52.578 45.212,28.702 44.958,28.448 42.799,28.448 42.291,28.956 v1(42.291,29.845)
CSN2: C30.1 R26.1 U2.3 | length 5.7
  Top Layer w0.35: U2.3@79,57.303 79.73,57.303 81.61,55.423 C30.1@82.042,55.423 82.88,55.423 83.058,55.245 R26.1@83.871,55.245
CSN2_N: L2.1 R24.2 R26.2 | length 41.6
  Top Layer w0.35: R26.2@85.293,55.245 v1(86.614,55.245)
  Top Layer w0.508: v1(93.091,29.591) R24.2@93.091,31.244
  Bottom Layer w0.35: v1(86.614,55.245) 87.137,55.768 89.281,55.768 89.296,55.753 92.745,55.753 96.043,52.455 96.043,28.825 95.666,28.448 93.472,28.448 93.091,28.829 v1(93.091,29.591)
CSP1: C12.2 R5.1 U1.4 | length 5.3
  Top Layer w0.35: U1.4@28.2,57.953 29.677,57.953 30.785,56.845 C12.2@31.242,56.845 R5.1@33.02,56.845
CSP2: C30.2 R25.1 U2.4 | length 5.3
  Top Layer w0.35: U2.4@79,57.953 80.223,57.953 81.331,56.845 C30.2@82.042,56.845 R25.1@83.82,56.845
FSYNC: C16.1 | length 1.2
  Top Layer w0.35: C16.1@34.62,68.326 v1(35.814,68.326)
GND: C3.2 C4.2 C5.2 C6.2 C7.2 C8.2 C9.2 C10.2 C13.2 C14.2 C15.2 C17.2 C22.2 C23.2 C24.2 C25.2 C26.2 C27.2 C28.2 C31.2 C32.2 C34.2 J2.1 J4.1 Q3.1 Q3.2 Q3.3 Q4.1 Q4.2 Q4.3 Q7.1 Q7.2 Q7.3 Q8.1 Q8.2 Q8.3 R4.1 R12.1 R16.1 R17.1 R20.2 R33.1 R34.1 TP2.1 TP4.1 U1.9 U1.15 U1.21 U2.2 U2.9 U2.15 U2.21 | length 33.8
  Top Layer w0.35: C14.2@19.944,59.253 20.099,59.408 21.259,59.408 21.414,59.253 U1.15@22.6,59.253 U1.21@25.075,59.253 ; 26.162,61.087 26.278,61.203 U1.9@28.2,61.203 29.159,61.203 30.905,62.948 ; C32.2@70.612,59.385 70.711,59.286 71.598,59.286 71.649,59.337 72.257,59.337 72.308,59.286 73.367,59.286 U2.15@73.4,59.253 U2.21@75.875,59.253 ; 76.708,56.642 76.719,56.653 U2.2@79,56.653 ; 77.089,61.214 77.1,61.203 U2.9@79,61.203 79.872,61.203 80.899,62.23
  Top Layer w2.286: C3.2@22.573,6.985 J2.1@31.75,6.985
  Bottom Layer w1.27: v2(1.905,22.86) v2(1.905,24.765)
  other v1: 24.4,57.428 25.4,57.428 26.4,57.428 75.2,57.428 76.2,57.428 77.2,57.428 24.4,58.428 25.4,58.428 26.4,58.428 75.2,58.428 76.2,58.428 77.2,58.428 24.4,59.428 25.4,59.428 26.4,59.428 75.2,59.428 76.2,59.428 77.2,59.428 24.4,60.428 25.4,60.428 26.4,60.428 75.2,60.428 76.2,60.428 77.2,60.428
  other v2: 62.23,1.905 69.85,1.905 37.465,2.54 40.64,2.54 44.45,2.54 48.26,2.54 52.07,2.54 55.245,2.54 58.42,2.54 72.39,3.175 78.74,3.175 38.735,4.445 41.91,4.445 45.72,4.445 49.53,4.445 53.34,4.445 56.515,4.445 59.69,4.445 40.64,6.35 44.45,6.35 48.26,6.35 52.07,6.35 55.245,6.35 73.025,6.35 1.905,15.24 1.905,17.145 1.905,19.05 31.877,19.431 53.34,20.193 84.455,20.193 1.905,20.955 82.804,20.955 31.877,21.59 84.455,22.098 53.34,22.225 31.115,23.114 82.804,23.241 54.991,23.368 53.34,24.257 31.115,24.765 42.926,73.025 60.96,73.025
LO1: R13.2 R15.2 U1.16 | length 85.1
  Top Layer w0.35: v1(20.955,58.674) 21.026,58.603 U1.16@22.6,58.603
  Top Layer w0.508: R13.2@27.686,28.397 v3(27.686,29.464) ; R15.2@35.56,28.397 v3(35.56,29.464)
  Bottom Layer w0.35: v1(18.669,59.309) 14.859,59.309 7.874,52.324 7.874,36.195 7.112,35.433 5.207,35.433 4.445,34.671 4.445,28.702 7.112,26.035 35.306,26.035 35.56,26.289 v3(35.56,29.464) ; 27.686,26.035 v3(27.686,29.464)
  Bottom Layer w0.508: v1(18.669,59.309) 20.32,59.309 v1(20.955,58.674)
LO2: R30.2 R32.2 U2.16 | length 85.7
  Top Layer w0.35: v1(71.953,58.603) U2.16@73.4,58.603
  Top Layer w0.508: R30.2@78.486,28.397 v3(78.486,29.464) ; R32.2@86.36,28.397 v3(86.36,29.464)
  Bottom Layer w0.35: v1(69.469,59.309) 64.332,59.309 58.674,53.651 58.674,36.576 57.404,35.306 55.88,35.306 54.991,34.417 54.991,28.829 57.785,26.035 78.486,26.035 ; v3(78.486,29.464) 78.486,26.035 ; v3(86.36,29.464) 86.36,26.797 85.598,26.035 78.486,26.035
  Bottom Layer w0.508: v1(69.469,59.309) 71.247,59.309 v1(71.953,58.603)
MODE1: R14.1 U1.13 | length 6.1
  Top Layer w0.35: R14.1@19.177,64.313 19.177,62.449 20.981,60.645 21.779,60.645 21.871,60.553 U1.13@22.6,60.553
MODE2: R31.1 U2.13 | length 6
  Top Layer w0.35: R31.1@69.977,64.313 69.977,62.611 72.035,60.553 U2.13@73.4,60.553
NetC1_2: C1.2 R1.1 | length 2.7
  Top Layer w0.508: R1.1@9.525,40.881 C1.2@9.525,43.561
NetC2_2: C2.2 R2.1 | length 2.6
  Top Layer w0.508: R2.1@17.018,40.754 C2.2@17.018,43.307
NetC18_1: C18.1 R18.1 R20.1 R21.1 U1.10 | length 17.9
  Top Layer w0.35: C18.1@24.714,64.643 26.492,64.643 R18.1@26.543,64.694 R20.1@28.321,64.694 ; R21.1@27.851,71.374 v1(27.851,72.771) ; U1.10@28.2,61.853 28.321,61.974 R20.1@28.321,64.694 ; v1(29.54,64.694) R20.1@28.321,64.694
  Bottom Layer w0.35: v1(27.851,72.771) 27.851,66.383 v1(29.54,64.694)
NetC19_2: C19.2 R19.1 | length 2.7
  Top Layer w0.508: R19.1@60.325,40.627 C19.2@60.325,43.307
NetC20_1: C20.1 R18.2 | length 2
  Top Layer w0.35: C20.1@24.714,66.421 25.527,66.421 25.832,66.116 R18.2@26.543,66.116
NetC21_2: C21.2 R23.1 | length 2.7
  Top Layer w0.508: R23.1@67.818,40.627 C21.2@67.818,43.307
NetC32_1: C32.1 D3.2 R31.2 U2.10 U2.17 | length 31.8
  Top Layer w0.35: D3.2@67.691,57.407 v1(69.339,57.407) 69.345,57.407 69.901,57.963 C32.1@70.612,57.963 ; R31.2@69.977,65.735 v1(69.977,66.929) ; C32.1@70.655,57.92 71.598,57.92 71.649,57.869 72.257,57.869 72.308,57.92 73.367,57.92 U2.17@73.4,57.953 ; U2.10@79,61.853 v1(79,62.859)
  Mid-Layer 1 w0.35: v1(69.339,57.407) 70.485,58.553 70.485,61.849 69.977,62.357 v1(69.977,66.929)
  Bottom Layer w0.508: v1(69.339,57.407) 72.012,57.407 73.406,58.801 73.406,61.341 74.924,62.859 v1(79,62.859)
NetD4_1: D4.1 R11.2 | length 2.8
  Top Layer w0.35: D4.1@40.002,56.261 40.843,57.102 R11.2@40.843,58.674
NetD5_1: D5.1 R29.2 | length 3.6
  Top Layer w0.508: R29.2@91.643,58.674 92.71,58.674 93.094,59.058 D5.1@93.094,61.087
NetIN1_1: IN1.1 R21.2 R22.2 | length 14.5
  Top Layer w0.35: R22.2@23.495,71.374 R21.2@26.251,71.374
  Top Layer w0.508: IN1.1@13.97,67.818 15.367,67.818 17.272,69.723 23.114,69.723 23.495,70.104 R22.2@23.495,71.374
NetQ1_4: Q1.4 R7.1 | length 2.5
  Top Layer w0.508: R7.1@5.461,31.674 5.519,31.674 6.35,32.505 6.35,32.512 6.707,32.869 Q1.4@7.493,32.869
NetQ2_4: Q2.4 R8.1 | length 2.5
  Top Layer w0.508: R8.1@13.335,31.674 13.393,31.674 14.588,32.869 Q2.4@15.367,32.869
NetQ3_4: Q3.4 R13.1 | length 2.1
  Top Layer w0.508: Q3.4@25.781,27.329 25.884,27.432 27.229,27.432 R13.1@27.686,26.975
NetQ4_4: Q4.4 R15.1 | length 2.2
  Top Layer w0.508: Q4.4@33.528,27.329 35.282,27.329 35.56,27.051 R15.1@35.56,26.975
NetQ5_4: Q5.4 R27.1 | length 2.4
  Top Layer w0.508: R27.1@56.261,31.928 56.319,31.928 57.26,32.869 Q5.4@58.293,32.869
NetQ6_4: Q6.4 R28.1 | length 2.4
  Top Layer w0.508: R28.1@64.135,31.928 64.313,31.928 65.254,32.869 Q6.4@66.167,32.869
NetQ7_4: Q7.4 R30.1 | length 2.1
  Top Layer w0.508: Q7.4@76.581,27.329 77.192,27.329 77.546,26.975 R30.1@78.486,26.975
NetQ8_4: Q8.4 R32.1 | length 2.2
  Top Layer w0.508: Q8.4@84.328,27.329 85.066,27.329 85.42,26.975 R32.1@86.36,26.975
NetR4_2: R4.2 R9.1 U1.2 | length 6.7
  Top Layer w0.35: U1.2@28.2,56.653 28.945,56.653 30.226,55.372 30.226,53.34 ; R9.1@29.159,53.34 30.226,53.34 ; R4.2@31.293,53.34 30.226,53.34
RES: C17.1 U1.14 U2.14 | length 67.8
  Top Layer w0.35: C17.1@17.399,64.313 17.399,63.373 v1(18.161,62.611) 20.731,60.041 21.48,60.041 21.618,59.903 U1.14@22.6,59.903 ; v1(68.453,65.278) 68.453,63.246 71.758,59.941 73.362,59.941 U2.14@73.4,59.903
  Bottom Layer w0.508: v1(18.161,62.611) 19.558,62.611 20.066,62.103 30.982,62.103 31.032,62.154 37.516,62.154 40.64,65.278 v1(68.453,65.278)
SLOPE1: R17.2 U1.12 | length 4.4
  Top Layer w0.35: R17.2@20.955,64.224 20.955,61.595 21.301,61.249 22.234,61.249 22.28,61.203 U1.12@22.6,61.203
SLOPE2: R34.2 U2.12 | length 4.3
  Top Layer w0.35: R34.2@71.755,64.224 71.755,61.849 72.401,61.203 U2.12@73.4,61.203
